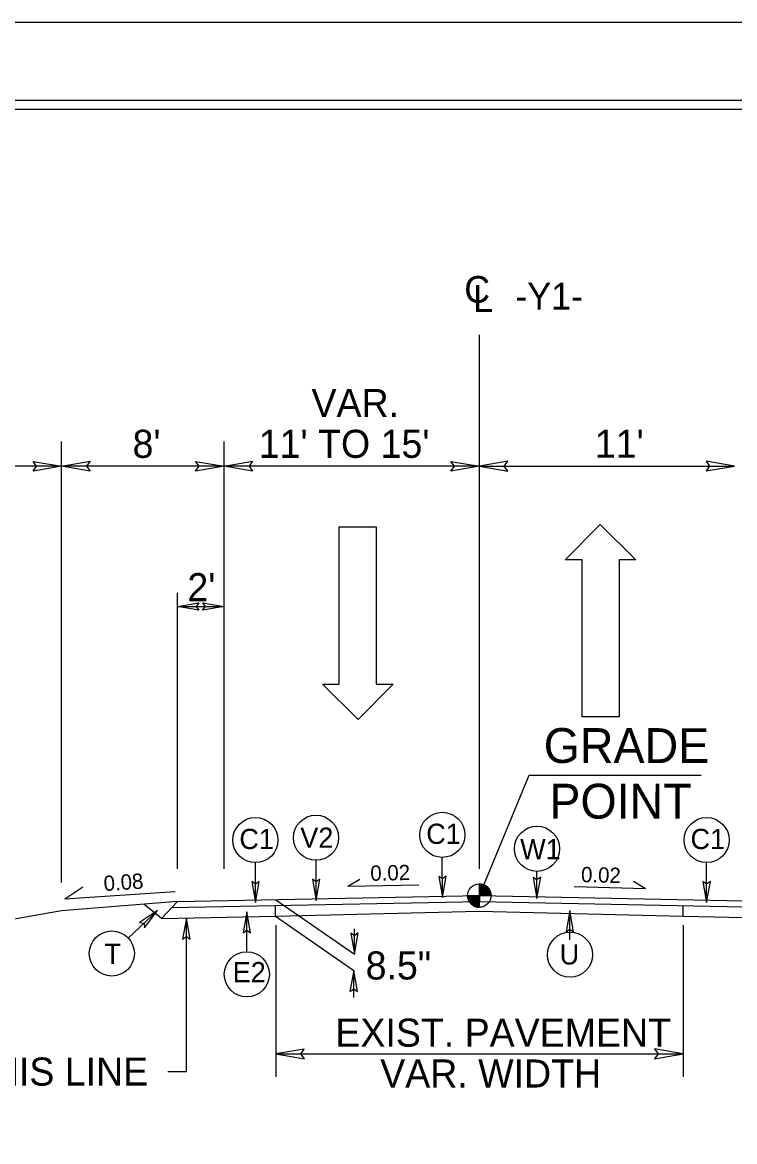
# Model space of a CAD drawing. Extents: x 3025871 to 3026431, y 707165 to 707825.
# Drawn here: x 3026143.53 to 3026174.22, y 707513.85 to 707562.05 of the extents above; entities that cross this region are included whole.
import ezdxf

# ---------------------------------------------------------------- set-up
doc = ezdxf.new("R2010")
doc.units = 0
for name, color, linetype in [('Old_Level_39', 7, 'Continuous'), ('Prop Drainage Structure Junction Box with Manhole CELL', 7, 'Continuous'), ('Prop Drainage Structure Junction Box with Manhole Label', 7, 'Continuous'), ('Prop Drainage Structure Junction Box with Slab Lid CELL', 7, 'Continuous'), ('Prop Drainage Structure Junction Box with Slab Lid TB 840 34 CELL', 7, 'Continuous'), ('Prop Drainage Structure Plot Symbol 20 Scale', 7, 'Continuous'), ('Prop Pavement Schedule Description CELL', 7, 'Continuous'), ('Sheet Cutting Line CELL', 7, 'Continuous'), ('Sheet Data Field CELL', 7, 'Continuous'), ('Sheet Sticker Incomplete CELL', 7, 'Continuous'), ('Sheet Typical CELL', 7, 'Continuous'), ('Typical Arrow Superelevation CELL', 7, 'Continuous'), ('Typical Grade Point Symbol CELL', 7, 'Continuous'), ('Typical Shoulder Slope CELL', 7, 'Continuous'), ('Typical Terminator CELL', 7, 'Continuous'), ('Typical Text Centerline CELL', 7, 'Continuous'), ('Typical Text Grade Point CELL', 7, 'Continuous')]:
    doc.layers.add(name, color=color, linetype=linetype)

msp = doc.modelspace()

# ---------------------------------------------------------------- linework, layer by layer
at = {"layer": 'Old_Level_39'}
msp.add_lwpolyline([(3026273.948, 707558.686), (3026023.973, 707558.686), (3026023.973, 707400.421), (3026273.948, 707400.421)], close=True, dxfattribs=at)
at = {"layer": 'Prop Drainage Structure Junction Box with Manhole CELL'}
for p, q in [((3026149.532, 707523.463), (3026148.782, 707524.07)), ((3026149.532, 707523.463), (3026154.441, 707523.561)), ((3026172.004, 707523.561), (3026187.948, 707523.242))]:
    msp.add_line(p, q, dxfattribs=at)
at = {"layer": 'Prop Drainage Structure Junction Box with Manhole Label'}
msp.add_line((3026163.221, 707525.601), (3026163.221, 707548.604), dxfattribs=at)
at = {"layer": 'Prop Drainage Structure Junction Box with Slab Lid CELL'}
for p, q in [((3026163.221, 707524.445), (3026163.221, 707524.949)), ((3026162.717, 707524.446), (3026163.221, 707524.445)), ((3026163.22, 707523.942), (3026163.221, 707524.445)), ((3026163.221, 707524.445), (3026163.22, 707523.942)), ((3026163.724, 707524.445), (3026163.221, 707524.445))]:
    msp.add_line(p, q, dxfattribs=at)
for points in [[(3026163.226, 707524.949), (3026163.226, 707524.949), (3026163.225, 707524.445)], [(3026163.236, 707524.949), (3026163.235, 707524.445)], [(3026163.246, 707524.948), (3026163.246, 707524.445)], [(3026163.256, 707524.948), (3026163.256, 707524.445)], [(3026163.266, 707524.947), (3026163.266, 707524.445)], [(3026163.276, 707524.946), (3026163.276, 707524.445)], [(3026163.286, 707524.944), (3026163.286, 707524.445)], [(3026163.296, 707524.943), (3026163.296, 707524.445)], [(3026163.306, 707524.942), (3026163.306, 707524.445)], [(3026163.316, 707524.94), (3026163.316, 707524.445)], [(3026163.326, 707524.938), (3026163.326, 707524.445)], [(3026163.336, 707524.935), (3026163.336, 707524.445)], [(3026163.346, 707524.933), (3026163.346, 707524.445)], [(3026163.356, 707524.93), (3026163.356, 707524.445)], [(3026163.366, 707524.928), (3026163.366, 707524.445)], [(3026163.377, 707524.924), (3026163.376, 707524.445)], [(3026163.387, 707524.921), (3026163.386, 707524.445)], [(3026163.397, 707524.918), (3026163.397, 707524.445)], [(3026163.407, 707524.913), (3026163.407, 707524.445)], [(3026163.417, 707524.909), (3026163.417, 707524.445)], [(3026163.427, 707524.904), (3026163.427, 707524.445)], [(3026163.437, 707524.9), (3026163.437, 707524.445)], [(3026163.447, 707524.895), (3026163.447, 707524.445)], [(3026163.457, 707524.89), (3026163.457, 707524.445)], [(3026163.467, 707524.884), (3026163.467, 707524.445)], [(3026163.477, 707524.878), (3026163.477, 707524.445)], [(3026163.487, 707524.873), (3026163.487, 707524.445)], [(3026163.497, 707524.866), (3026163.497, 707524.445)], [(3026163.507, 707524.859), (3026163.507, 707524.445)], [(3026163.518, 707524.852), (3026163.517, 707524.445)], [(3026163.528, 707524.845), (3026163.527, 707524.445)], [(3026163.538, 707524.837), (3026163.538, 707524.445)], [(3026162.72, 707524.446), (3026162.72, 707524.391)], [(3026162.73, 707524.446), (3026162.73, 707524.331)], [(3026162.74, 707524.446), (3026162.74, 707524.296)], [(3026162.75, 707524.446), (3026162.75, 707524.265)], [(3026162.76, 707524.446), (3026162.76, 707524.242)], [(3026162.77, 707524.446), (3026162.77, 707524.221)], [(3026162.78, 707524.446), (3026162.78, 707524.202)], [(3026162.79, 707524.446), (3026162.79, 707524.184)], [(3026162.8, 707524.446), (3026162.8, 707524.168)], [(3026162.81, 707524.446), (3026162.81, 707524.154)], [(3026162.82, 707524.446), (3026162.82, 707524.14)], [(3026162.83, 707524.446), (3026162.83, 707524.128)], [(3026162.84, 707524.446), (3026162.84, 707524.115)], [(3026162.85, 707524.446), (3026162.85, 707524.104)], [(3026162.861, 707524.446), (3026162.86, 707524.093)], [(3026162.871, 707524.446), (3026162.871, 707524.083)], [(3026162.881, 707524.446), (3026162.881, 707524.074)], [(3026162.891, 707524.446), (3026162.891, 707524.065)], [(3026162.901, 707524.446), (3026162.901, 707524.056)], [(3026162.911, 707524.446), (3026162.911, 707524.048)], [(3026162.921, 707524.446), (3026162.921, 707524.04)], [(3026162.931, 707524.446), (3026162.931, 707524.034)], [(3026162.941, 707524.446), (3026162.941, 707524.027)], [(3026162.951, 707524.446), (3026162.951, 707524.02)], [(3026162.961, 707524.446), (3026162.961, 707524.014)], [(3026162.971, 707524.446), (3026162.971, 707524.008)], [(3026162.981, 707524.445), (3026162.981, 707524.002)], [(3026162.992, 707524.445), (3026162.991, 707523.997)], [(3026163.002, 707524.445), (3026163.001, 707523.992)], [(3026163.012, 707524.445), (3026163.012, 707523.988)], [(3026163.022, 707524.445), (3026163.022, 707523.983)], [(3026163.032, 707524.445), (3026163.032, 707523.979)], [(3026163.042, 707524.445), (3026163.042, 707523.974)], [(3026163.052, 707524.445), (3026163.052, 707523.971)], [(3026163.062, 707524.445), (3026163.062, 707523.968)], [(3026163.072, 707524.445), (3026163.072, 707523.964)], [(3026163.082, 707524.445), (3026163.082, 707523.962)], [(3026163.092, 707524.445), (3026163.092, 707523.959)], [(3026163.102, 707524.445), (3026163.102, 707523.957)], [(3026163.112, 707524.445), (3026163.112, 707523.954)], [(3026163.122, 707524.445), (3026163.122, 707523.952)], [(3026163.132, 707524.445), (3026163.132, 707523.95)], [(3026163.143, 707524.445), (3026163.142, 707523.949)], [(3026163.153, 707524.445), (3026163.152, 707523.946)], [(3026163.163, 707524.445), (3026163.163, 707523.945)], [(3026163.173, 707524.445), (3026163.173, 707523.944)], [(3026163.183, 707524.445), (3026163.183, 707523.943)], [(3026163.193, 707524.445), (3026163.193, 707523.943)], [(3026163.203, 707524.445), (3026163.203, 707523.942)], [(3026163.213, 707524.445), (3026163.213, 707523.942), (3026163.213, 707523.942)], [(3026163.548, 707524.828), (3026163.548, 707524.445)], [(3026163.558, 707524.819), (3026163.558, 707524.445)], [(3026163.568, 707524.81), (3026163.568, 707524.445)], [(3026163.578, 707524.8), (3026163.578, 707524.445)], [(3026163.588, 707524.79), (3026163.588, 707524.445)], [(3026163.598, 707524.779), (3026163.598, 707524.445)], [(3026163.608, 707524.766), (3026163.608, 707524.445)], [(3026163.618, 707524.754), (3026163.618, 707524.445)], [(3026163.628, 707524.741), (3026163.628, 707524.445)], [(3026163.638, 707524.726), (3026163.638, 707524.445)], [(3026163.648, 707524.71), (3026163.648, 707524.445)], [(3026163.658, 707524.694), (3026163.658, 707524.445)], [(3026163.669, 707524.676), (3026163.668, 707524.445)], [(3026163.679, 707524.655), (3026163.679, 707524.445)], [(3026163.689, 707524.631), (3026163.689, 707524.445)], [(3026163.699, 707524.603), (3026163.699, 707524.445)], [(3026163.709, 707524.568), (3026163.709, 707524.445)], [(3026163.719, 707524.517), (3026163.719, 707524.445)]]:
    msp.add_lwpolyline(points, dxfattribs=at)
msp.add_circle((3026163.22, 707524.446), 0.504, dxfattribs=at)
for start, end in [(359.9709, 89.9709), (179.9709, 269.9709)]:
    msp.add_arc((3026163.22, 707524.446), 0.504, start, end, dxfattribs=at)
at = {"layer": 'Prop Drainage Structure Junction Box with Slab Lid TB 840 34 CELL'}
for p, q in [((3026145.221, 707525.007), (3026145.221, 707544.01)), ((3026152.221, 707525.601), (3026152.221, 707544.01)), ((3026145.221, 707542.937), (3026133.221, 707542.937)), ((3026163.221, 707542.937), (3026145.221, 707542.937)), ((3026163.221, 707542.943), (3026174.221, 707542.943)), ((3026150.221, 707525.601), (3026150.221, 707537.48)), ((3026150.221, 707536.897), (3026152.221, 707536.899)), ((3026154.451, 707524.27), (3026157.836, 707521.921)), ((3026154.441, 707523.561), (3026157.809, 707521.226)), ((3026154.448, 707523.166), (3026154.448, 707516.645)), ((3026157.836, 707521.921), (3026157.836, 707523.014)), ((3026171.997, 707523.166), (3026171.997, 707516.645)), ((3026154.448, 707517.627), (3026171.997, 707517.627)), ((3026150.601, 707516.853), (3026149.791, 707516.853))]:
    msp.add_line(p, q, dxfattribs=at)
at = {"layer": 'Prop Drainage Structure Plot Symbol 20 Scale'}
msp.add_line((3026163.221, 707524.445), (3026165.365, 707529.633), dxfattribs=at)
at = {"layer": 'Prop Pavement Schedule Description CELL'}
for p, q in [((3026150.221, 707524.185), (3026163.221, 707524.445)), ((3026163.221, 707524.445), (3026187.221, 707523.965)), ((3026150.221, 707524.185), (3026149.532, 707523.463)), ((3026149.963, 707523.93), (3026163.221, 707524.195)), ((3026154.441, 707523.561), (3026154.444, 707524.02)), ((3026163.22, 707524.195), (3026187.476, 707523.71)), ((3026172, 707523.561), (3026171.998, 707524.02))]:
    msp.add_line(p, q, dxfattribs=at)
msp.add_lwpolyline([(3026154.441, 707523.561), (3026163.218, 707523.781), (3026172.004, 707523.561)], dxfattribs=at)
at = {"layer": 'Sheet Cutting Line CELL'}
msp.add_lwpolyline([(3026272.073, 707558.304), (3026047.073, 707558.304), (3026047.073, 707400.804), (3026272.073, 707400.804)], close=True, dxfattribs=at)
at = {"layer": 'Sheet Data Field CELL'}
for p, q in [((3026157.182, 707533.559), (3026157.182, 707540.329)), ((3026157.182, 707540.329), (3026158.778, 707540.329)), ((3026158.778, 707540.329), (3026158.778, 707533.559)), ((3026166.924, 707538.909), (3026168.423, 707540.432)), ((3026168.423, 707540.432), (3026169.971, 707538.909)), ((3026167.65, 707538.909), (3026166.924, 707538.909)), ((3026167.65, 707532.139), (3026167.65, 707538.909)), ((3026169.971, 707538.909), (3026169.245, 707538.909)), ((3026169.245, 707538.909), (3026169.245, 707532.139)), ((3026158.004, 707532.035), (3026156.456, 707533.559)), ((3026156.456, 707533.559), (3026157.182, 707533.559)), ((3026159.503, 707533.559), (3026158.004, 707532.035)), ((3026158.778, 707533.559), (3026159.503, 707533.559)), ((3026169.245, 707532.139), (3026167.65, 707532.139))]:
    msp.add_line(p, q, dxfattribs=at)
at = {"layer": 'Sheet Sticker Incomplete CELL'}
for p, q in [((3026157.549, 707524.846), (3026158.064, 707525.158)), ((3026157.549, 707524.846), (3026160.617, 707524.907)), ((3026170.375, 707524.74), (3026169.861, 707525.055)), ((3026145.361, 707524.301), (3026146.137, 707524.822)), ((3026145.361, 707524.301), (3026150.109, 707524.623)), ((3026170.375, 707524.74), (3026167.308, 707524.817))]:
    msp.add_line(p, q, dxfattribs=at)
at = {"layer": 'Sheet Typical CELL'}
msp.add_line((3026150.221, 707524.185), (3026145.221, 707523.785), dxfattribs=at)
at = {"layer": 'Typical Grade Point Symbol CELL'}
for p, q in [((3026153.573, 707524.142), (3026153.572, 707525.866)), ((3026156.184, 707524.241), (3026156.183, 707525.965)), ((3026161.627, 707524.365), (3026161.626, 707526.089)), ((3026173.015, 707524.142), (3026173.014, 707525.866)), ((3026165.704, 707524.322), (3026165.704, 707525.491)), ((3026148.095, 707522.619), (3026149.353, 707523.798)), ((3026150.601, 707516.853), (3026150.597, 707523.48)), ((3026153.204, 707522.028), (3026153.203, 707523.753)), ((3026167.127, 707522.54), (3026167.127, 707523.801)), ((3026157.809, 707520.054), (3026157.809, 707521.226))]:
    msp.add_line(p, q, dxfattribs=at)
for centre in [(3026153.572, 707526.838), (3026156.183, 707526.937), (3026161.626, 707527.061), (3026173.014, 707526.838), (3026165.704, 707526.463), (3026147.386, 707521.954), (3026167.129, 707521.901), (3026153.204, 707521.056)]:
    msp.add_circle(centre, 0.972, dxfattribs=at)
at = {"layer": 'Typical Shoulder Slope CELL'}
msp.add_line((3026165.365, 707529.633), (3026172.778, 707529.63), dxfattribs=at)
at = {"layer": 'Typical Terminator CELL'}
msp.add_lwpolyline([(3026274.623, 707562.054), (3026022.023, 707562.054), (3026022.023, 707397.054), (3026274.623, 707397.054)], close=True, dxfattribs=at)
at = {"layer": 'Typical Text Centerline CELL'}
for points in [[(3026143.996, 707543.148), (3026145.221, 707542.937), (3026143.989, 707542.72), (3026144.145, 707542.937)], [(3026146.446, 707542.726), (3026145.221, 707542.937), (3026146.453, 707543.155), (3026146.296, 707542.937)], [(3026150.996, 707543.148), (3026152.221, 707542.937), (3026150.989, 707542.72), (3026151.145, 707542.937)], [(3026153.446, 707542.726), (3026152.221, 707542.937), (3026153.453, 707543.155), (3026153.296, 707542.937)], [(3026161.996, 707543.148), (3026163.221, 707542.937), (3026161.989, 707542.72), (3026162.145, 707542.937)], [(3026164.446, 707543.154), (3026163.221, 707542.943), (3026164.453, 707542.726), (3026164.296, 707542.943)], [(3026172.996, 707542.733), (3026174.221, 707542.943), (3026172.989, 707543.161), (3026173.145, 707542.943)], [(3026151.132, 707536.741), (3026150.213, 707536.899), (3026151.137, 707537.062), (3026151.019, 707536.899)], [(3026151.303, 707537.057), (3026152.222, 707536.899), (3026151.298, 707536.736), (3026151.415, 707536.899)], [(3026153.416, 707525.051), (3026153.573, 707524.142), (3026153.735, 707525.056), (3026153.573, 707524.94)], [(3026156.026, 707525.15), (3026156.184, 707524.241), (3026156.345, 707525.156), (3026156.183, 707525.039)], [(3026161.47, 707525.274), (3026161.627, 707524.365), (3026161.789, 707525.279), (3026161.627, 707525.163)], [(3026165.547, 707525.232), (3026165.704, 707524.322), (3026165.865, 707525.237), (3026165.704, 707525.12)], [(3026172.858, 707525.051), (3026173.015, 707524.142), (3026173.176, 707525.056), (3026173.015, 707524.94)], [(3026148.797, 707523.062), (3026149.353, 707523.798), (3026148.575, 707523.291), (3026148.771, 707523.252)], [(3026150.754, 707522.57), (3026150.597, 707523.48), (3026150.436, 707522.565), (3026150.597, 707522.681)], [(3026153.36, 707522.843), (3026153.203, 707523.753), (3026153.042, 707522.838), (3026153.204, 707522.954)], [(3026167.284, 707522.892), (3026167.127, 707523.801), (3026166.965, 707522.887), (3026167.127, 707523.003)], [(3026157.679, 707522.831), (3026157.836, 707521.921), (3026157.998, 707522.836), (3026157.836, 707522.72)], [(3026157.966, 707520.316), (3026157.809, 707521.226), (3026157.647, 707520.311), (3026157.809, 707520.427)], [(3026155.673, 707517.838), (3026154.448, 707517.627), (3026155.68, 707517.409), (3026155.523, 707517.627)], [(3026170.772, 707517.416), (3026171.997, 707517.627), (3026170.765, 707517.845), (3026170.922, 707517.627)]]:
    msp.add_lwpolyline(points, close=True, dxfattribs=at)
at = {"layer": 'Typical Text Grade Point CELL'}
msp.add_line((3026145.221, 707523.785), (3026133.221, 707521.695), dxfattribs=at)

# ---------------------------------------------------------------- texts
at = {"layer": 'Prop Drainage Structure Junction Box with Manhole Label'}
msp.add_text('C', height=1.152, dxfattribs=at).set_placement((3026162.571, 707549.978))
for s, height, p in [('L', 1.152, (3026162.954, 707549.585)), ('-Y1-', 1.1523, (3026164.772, 707549.687))]:
    msp.add_text(s, height=height, rotation=359.9469, dxfattribs=at).set_placement(p)
at = {"layer": 'Prop Drainage Structure Junction Box with Slab Lid TB 840 34 CELL'}
for s, height, p in [('VAR.', 1.2089, (3026155.989, 707545.056)), ("8'", 1.2089, (3026148.278, 707543.299)), ("11' TO 15'", 1.2089, (3026153.716, 707543.299)), ("11'", 1.2089, (3026168.198, 707543.305)), ("2'", 1.2089, (3026150.64, 707537.125)), ('8.5"', 1.2089, (3026158.322, 707520.833)), ('EXIST. PAVEMENT', 1.20892, (3026157.018, 707517.939)), ('GRADE TO THIS LINE', 1.20892, (3026132.334, 707516.263)), ('VAR. WIDTH', 1.2089, (3026158.949, 707516.181))]:
    msp.add_text(s, height=height, dxfattribs=at).set_placement(p)
at = {"layer": 'Sheet Sticker Incomplete CELL'}
for s, rotation, p in [('0.08', 3.8796, (3026147.053, 707524.637)), ('0.02 ', 1.2029, (3026158.529, 707525.082)), ('0.02', 358.5679, (3026167.597, 707525.028))]:
    msp.add_text(s, height=0.6583, rotation=rotation, dxfattribs=at).set_placement(p)
at = {"layer": 'Typical Arrow Superelevation CELL'}
for s, p in [('C1', (3026152.88, 707526.45)), ('V2', (3026155.506, 707526.507)), ('C1', (3026160.934, 707526.673)), ('C1', (3026172.322, 707526.45)), ('W1', (3026164.981, 707526.011)), ('U', (3026166.681, 707521.481)), ('E2', (3026152.595, 707520.717))]:
    msp.add_text(s, height=0.87, dxfattribs=at).set_placement(p)
msp.add_text('T', height=0.87, rotation=360, dxfattribs=at).set_placement((3026147.064, 707521.506))
at = {"layer": 'Typical Shoulder Slope CELL'}
for s, p in [('GRADE', (3026165.994, 707530.159)), ('POINT', (3026166.239, 707527.763))]:
    msp.add_text(s, height=1.5, rotation=359.9804, dxfattribs=at).set_placement(p)

doc.saveas('drawing.dxf')
